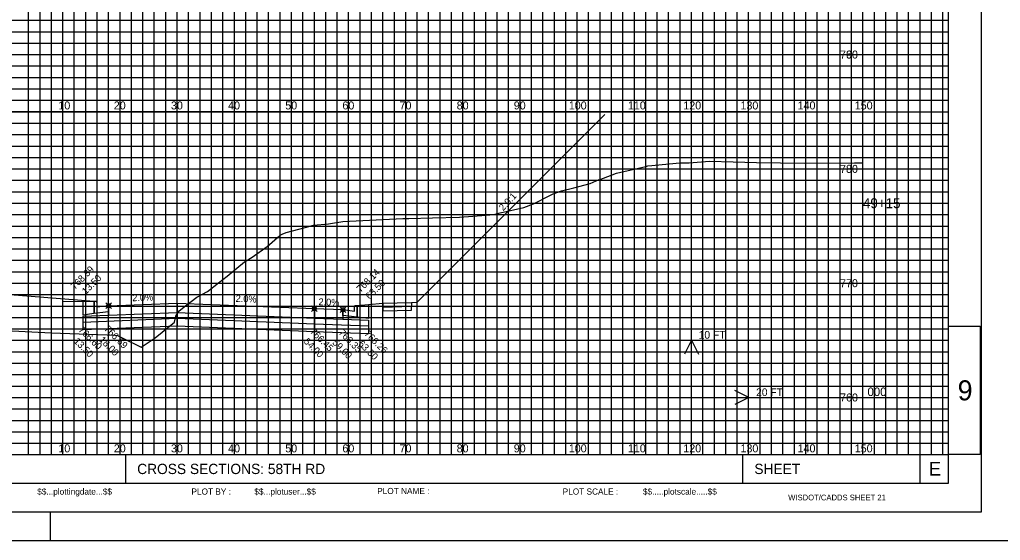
# Model space of a CAD drawing. Extents: x 578243 to 601557, y 174899 to 175559.
# Drawn here: x 600362.3 to 600533.9, y 174898.8 to 174989.9 of the extents above; entities that cross this region are included whole.
import ezdxf

# ---------------------------------------------------------------- set-up
doc = ezdxf.new("R2010")
doc.units = 0
for name, color, linetype in [('E_PROF_Grid', 7, 'Continuous'), ('E_PROF_GridMin', 7, 'Continuous'), ('P_CRDR_Label', 7, 'Continuous'), ('P_CRDR_Link', 7, 'Continuous'), ('P_E_XS_Ground', 7, 'Continuous'), ('P_RW_SlopeIntercepts', 7, 'Continuous'), ('P_XS_Text', 7, 'Continuous'), ('PLT_Sheet_Border', 7, 'Continuous'), ('PLT_Sheet_Info', 7, 'Continuous')]:
    doc.layers.add(name, color=color, linetype=linetype)

msp = doc.modelspace()

# ---------------------------------------------------------------- linework, layer by layer
at = {"layer": 'E_PROF_Grid'}
for p, q in [((600369.84, 174913.8), (600369.84, 175108.8)), ((600379.84, 174913.8), (600379.84, 175108.8)), ((600389.84, 174913.8), (600389.84, 175108.8)), ((600399.84, 174913.8), (600399.84, 175108.8)), ((600409.84, 174913.8), (600409.84, 175108.8)), ((600419.84, 174913.8), (600419.84, 175108.8)), ((600429.84, 174913.8), (600429.84, 175108.8)), ((600439.84, 174913.8), (600439.84, 175108.8)), ((600449.84, 174913.8), (600449.84, 175108.8)), ((600459.84, 174913.8), (600459.84, 175108.8)), ((600469.84, 174913.8), (600469.84, 175108.8)), ((600479.84, 174913.8), (600479.84, 175108.8)), ((600489.84, 174913.8), (600489.84, 175108.8)), ((600499.84, 174913.8), (600499.84, 175108.8)), ((600509.84, 174913.8), (600509.84, 175108.8)), ((600519.84, 174913.8), (600519.84, 175108.8)), ((600209.84, 174983.8), (600524.84, 174983.8)), ((600209.84, 174973.8), (600524.84, 174973.8)), ((600209.84, 174963.8), (600524.84, 174963.8)), ((600209.84, 174953.8), (600524.84, 174953.8)), ((600209.84, 174943.8), (600524.84, 174943.8)), ((600209.84, 174933.8), (600524.84, 174933.8)), ((600209.84, 174923.8), (600524.84, 174923.8))]:
    msp.add_line(p, q, dxfattribs=at)
at = {"layer": 'E_PROF_GridMin'}
for p, q in [((600363.84, 174913.8), (600363.84, 175108.8)), ((600365.84, 174913.8), (600365.84, 175108.8)), ((600367.84, 174913.8), (600367.84, 175108.8)), ((600371.84, 174913.8), (600371.84, 175108.8)), ((600373.84, 174913.8), (600373.84, 175108.8)), ((600375.84, 174913.8), (600375.84, 175108.8)), ((600377.84, 174913.8), (600377.84, 175108.8)), ((600381.84, 174913.8), (600381.84, 175108.8)), ((600383.84, 174913.8), (600383.84, 175108.8)), ((600385.84, 174913.8), (600385.84, 175108.8)), ((600387.84, 174913.8), (600387.84, 175108.8)), ((600391.84, 174913.8), (600391.84, 175108.8)), ((600393.84, 174913.8), (600393.84, 175108.8)), ((600395.84, 174913.8), (600395.84, 175108.8)), ((600397.84, 174913.8), (600397.84, 175108.8)), ((600401.84, 174913.8), (600401.84, 175108.8)), ((600403.84, 174913.8), (600403.84, 175108.8)), ((600405.84, 174913.8), (600405.84, 175108.8)), ((600407.84, 174913.8), (600407.84, 175108.8)), ((600411.84, 174913.8), (600411.84, 175108.8)), ((600413.84, 174913.8), (600413.84, 175108.8)), ((600415.84, 174913.8), (600415.84, 175108.8)), ((600417.84, 174913.8), (600417.84, 175108.8)), ((600421.84, 174913.8), (600421.84, 175108.8)), ((600423.84, 174913.8), (600423.84, 175108.8)), ((600425.84, 174913.8), (600425.84, 175108.8)), ((600427.84, 174913.8), (600427.84, 175108.8)), ((600431.84, 174913.8), (600431.84, 175108.8)), ((600433.84, 174913.8), (600433.84, 175108.8)), ((600435.84, 174913.8), (600435.84, 175108.8)), ((600437.84, 174913.8), (600437.84, 175108.8)), ((600441.84, 174913.8), (600441.84, 175108.8)), ((600443.84, 174913.8), (600443.84, 175108.8)), ((600445.84, 174913.8), (600445.84, 175108.8)), ((600447.84, 174913.8), (600447.84, 175108.8)), ((600451.84, 174913.8), (600451.84, 175108.8)), ((600453.84, 174913.8), (600453.84, 175108.8)), ((600455.84, 174913.8), (600455.84, 175108.8)), ((600457.84, 174913.8), (600457.84, 175108.8)), ((600461.84, 174913.8), (600461.84, 175108.8)), ((600463.84, 174913.8), (600463.84, 175108.8)), ((600465.84, 174913.8), (600465.84, 175108.8)), ((600467.84, 174913.8), (600467.84, 175108.8)), ((600471.84, 174913.8), (600471.84, 175108.8)), ((600473.84, 174913.8), (600473.84, 175108.8)), ((600475.84, 174913.8), (600475.84, 175108.8)), ((600477.84, 174913.8), (600477.84, 175108.8)), ((600481.84, 174913.8), (600481.84, 175108.8)), ((600483.84, 174913.8), (600483.84, 175108.8)), ((600485.84, 174913.8), (600485.84, 175108.8)), ((600487.84, 174913.8), (600487.84, 175108.8)), ((600491.84, 174913.8), (600491.84, 175108.8)), ((600493.84, 174913.8), (600493.84, 175108.8)), ((600495.84, 174913.8), (600495.84, 175108.8)), ((600497.84, 174913.8), (600497.84, 175108.8)), ((600501.84, 174913.8), (600501.84, 175108.8)), ((600503.84, 174913.8), (600503.84, 175108.8)), ((600505.84, 174913.8), (600505.84, 175108.8)), ((600507.84, 174913.8), (600507.84, 175108.8)), ((600511.84, 174913.8), (600511.84, 175108.8)), ((600513.84, 174913.8), (600513.84, 175108.8)), ((600515.84, 174913.8), (600515.84, 175108.8)), ((600517.84, 174913.8), (600517.84, 175108.8)), ((600521.84, 174913.8), (600521.84, 175108.8)), ((600523.84, 174913.8), (600523.84, 175108.8)), ((600209.84, 174989.8), (600524.84, 174989.8)), ((600209.84, 174987.8), (600524.84, 174987.8)), ((600209.84, 174985.8), (600524.84, 174985.8)), ((600209.84, 174981.8), (600524.84, 174981.8)), ((600209.84, 174979.8), (600524.84, 174979.8)), ((600209.84, 174977.8), (600524.84, 174977.8)), ((600209.84, 174975.8), (600524.84, 174975.8)), ((600209.84, 174971.8), (600524.84, 174971.8)), ((600209.84, 174969.8), (600524.84, 174969.8)), ((600209.84, 174967.8), (600524.84, 174967.8)), ((600209.84, 174965.8), (600524.84, 174965.8)), ((600209.84, 174961.8), (600524.84, 174961.8)), ((600209.84, 174959.8), (600524.84, 174959.8)), ((600209.84, 174957.8), (600524.84, 174957.8)), ((600209.84, 174955.8), (600524.84, 174955.8)), ((600209.84, 174951.8), (600524.84, 174951.8)), ((600209.84, 174949.8), (600524.84, 174949.8)), ((600209.84, 174947.8), (600524.84, 174947.8)), ((600209.84, 174945.8), (600524.84, 174945.8)), ((600209.84, 174941.8), (600524.84, 174941.8)), ((600209.84, 174939.8), (600524.84, 174939.8)), ((600209.84, 174937.8), (600524.84, 174937.8)), ((600209.84, 174935.8), (600524.84, 174935.8)), ((600209.84, 174931.8), (600524.84, 174931.8)), ((600209.84, 174929.8), (600524.84, 174929.8)), ((600209.84, 174927.8), (600524.84, 174927.8)), ((600209.84, 174925.8), (600524.84, 174925.8)), ((600209.84, 174921.8), (600524.84, 174921.8)), ((600209.84, 174919.8), (600524.84, 174919.8)), ((600209.84, 174917.8), (600524.84, 174917.8)), ((600209.84, 174915.8), (600524.84, 174915.8)), ((600527.19, 174898.8), (600537.19, 174898.8))]:
    msp.add_line(p, q, dxfattribs=at)
at = {"layer": 'P_CRDR_Label'}
for points in [[(600377.35, 174939.35), (600378.34, 174940.34)], [(600377.35, 174940.34), (600378.34, 174939.35)], [(600413.35, 174938.87), (600414.34, 174939.86)], [(600413.35, 174939.86), (600414.34, 174938.87)], [(600418.35, 174938.67), (600419.34, 174939.66)], [(600418.35, 174939.66), (600419.34, 174938.67)]]:
    msp.add_lwpolyline(points, dxfattribs=at)
for centre in [(600377.84, 174939.85), (600413.84, 174939.37), (600418.84, 174939.17)]:
    msp.add_circle(centre, 0.35, dxfattribs=at)
at = {"layer": 'P_CRDR_Link'}
msp.add_line((600464.69, 174973.31), (600431.84, 174940.46), dxfattribs=at)
for points in [[(600375.34, 174940.6), (600359.84, 174941.84)], [(600375.34, 174940.6), (600359.84, 174941.84)], [(600373.34, 174940.58), (600369.84, 174940.55)], [(600373.34, 174940.58), (600369.84, 174940.55)], [(600375.34, 174940.6), (600373.34, 174940.58)], [(600373.34, 174940.58), (600373.34, 174938.28)], [(600373.34, 174940.58), (600373.34, 174938.28)], [(600373.34, 174940.58), (600373.34, 174938.28)], [(600375.66, 174940.6), (600375.34, 174940.6)], [(600375.66, 174940.6), (600375.34, 174940.6)], [(600375.34, 174940.6), (600375.34, 174938.53)], [(600375.34, 174938.53), (600375.34, 174940.6)], [(600375.74, 174940.55), (600375.66, 174940.6)], [(600375.74, 174940.55), (600375.66, 174940.6)], [(600375.8, 174940.44), (600375.74, 174940.55)], [(600375.8, 174940.44), (600375.74, 174940.55)], [(600375.83, 174940.28), (600375.8, 174940.44)], [(600375.83, 174940.28), (600375.8, 174940.44)], [(600375.84, 174939.6), (600375.83, 174940.28)], [(600375.84, 174939.6), (600375.83, 174940.28)], [(600377.84, 174939.85), (600375.84, 174939.6)], [(600377.84, 174939.85), (600375.84, 174939.6)], [(600377.84, 174939.85), (600389.84, 174940.33)], [(600377.84, 174938.85), (600377.84, 174939.85)], [(600377.84, 174939.85), (600377.84, 174938.18)], [(600389.84, 174940.33), (600389.84, 174938.66)], [(600389.84, 174940.33), (600413.84, 174939.37)], [(600389.84, 174940.33), (600389.84, 174938.66)], [(600420.85, 174939.6), (600420.88, 174939.76)], [(600420.85, 174939.6), (600420.88, 174939.76)], [(600420.88, 174939.76), (600420.94, 174939.87)], [(600420.88, 174939.76), (600420.94, 174939.87)], [(600420.94, 174939.87), (600421.02, 174939.92)], [(600420.94, 174939.87), (600421.02, 174939.92)], [(600421.02, 174939.92), (600421.34, 174939.92)], [(600421.02, 174939.92), (600421.34, 174939.92)], [(600421.34, 174939.92), (600423.34, 174940.08)], [(600421.34, 174939.92), (600421.34, 174937.85)], [(600421.34, 174937.85), (600421.34, 174939.92)], [(600423.34, 174940.08), (600425.84, 174940.28)], [(600423.34, 174940.08), (600425.84, 174940.28)], [(600423.34, 174940.08), (600423.34, 174937.6)], [(600423.34, 174940.08), (600423.34, 174937.6)], [(600423.34, 174940.08), (600423.34, 174937.6)], [(600425.84, 174940.28), (600430.84, 174940.43)], [(600425.84, 174940.28), (600430.84, 174940.43)], [(600425.84, 174940.28), (600425.85, 174939.61)], [(600425.85, 174939.61), (600430.84, 174939.76)], [(600430.83, 174939.1), (600430.84, 174939.76)], [(600430.84, 174940.43), (600431.84, 174940.46)], [(600430.84, 174940.43), (600431.84, 174940.46)], [(600430.84, 174940.43), (600430.84, 174939.76)], [(600373.34, 174938.28), (600375.34, 174938.53)], [(600373.34, 174938), (600377.84, 174938.18)], [(600375.34, 174938.53), (600377.84, 174938.85)], [(600375.34, 174938.53), (600377.84, 174938.85)], [(600377.84, 174938.18), (600389.84, 174938.66)], [(600389.84, 174938.66), (600389.84, 174937.66)], [(600389.84, 174938.66), (600413.84, 174937.7)], [(600389.84, 174938.66), (600389.84, 174937.66)], [(600413.84, 174939.37), (600413.84, 174937.7)], [(600413.84, 174939.37), (600418.84, 174939.17)], [(600413.84, 174939.37), (600413.84, 174937.7)], [(600418.84, 174939.17), (600418.84, 174937.5)], [(600418.84, 174939.17), (600420.84, 174938.92)], [(600418.84, 174939.17), (600420.84, 174938.92)], [(600418.84, 174938.17), (600418.84, 174939.17)], [(600421.34, 174937.85), (600418.84, 174938.17)], [(600421.34, 174937.85), (600418.84, 174938.17)], [(600420.84, 174938.92), (600420.85, 174939.6)], [(600420.84, 174938.92), (600420.85, 174939.6)], [(600425.85, 174939.61), (600425.85, 174938.95)], [(600425.85, 174938.95), (600430.83, 174939.1)], [(600373.34, 174938), (600373.34, 174937)], [(600373.34, 174937), (600389.84, 174937.66)], [(600373.34, 174937), (600373.34, 174935.67)], [(600373.34, 174935.67), (600389.84, 174936.33)], [(600389.84, 174937.66), (600389.84, 174936.33)], [(600389.84, 174937.66), (600413.84, 174936.7)], [(600389.84, 174937.66), (600389.84, 174936.33)], [(600389.84, 174936.33), (600413.84, 174935.37)], [(600413.84, 174937.7), (600413.84, 174936.7)], [(600413.84, 174937.7), (600418.84, 174937.5)], [(600413.84, 174937.7), (600413.84, 174936.7)], [(600413.84, 174936.7), (600413.84, 174935.37)], [(600413.84, 174936.7), (600423.34, 174936.32)], [(600413.84, 174936.7), (600413.84, 174935.37)], [(600418.84, 174937.5), (600423.34, 174937.32)], [(600423.34, 174937.6), (600421.34, 174937.85)], [(600423.34, 174937.32), (600423.34, 174936.32)], [(600423.34, 174936.32), (600423.34, 174934.99)], [(600413.84, 174935.37), (600423.34, 174934.99)]]:
    msp.add_lwpolyline(points, dxfattribs=at)
at = {"layer": 'P_E_XS_Ground'}
msp.add_lwpolyline([(600359.84, 174935.54), (600367.8, 174935.14), (600377.57, 174934.75), (600378.93, 174934.68), (600379.38, 174934.67), (600380.33, 174934.19), (600383.51, 174932.6), (600385.99, 174934.24), (600389.38, 174936.95), (600389.62, 174938.05), (600390.15, 174938.93), (600391.04, 174939.66), (600393.29, 174941.36), (600395.14, 174942.35), (600397.06, 174943.88), (600398.57, 174945.03), (600401.64, 174947.52), (600402.96, 174948.37), (600405.59, 174950.24), (600407.8, 174952.15), (600408.19, 174952.4), (600408.91, 174952.66), (600412.24, 174953.56), (600413.68, 174953.97), (600416.3, 174954.18), (600418.81, 174954.62), (600429.3, 174955.09), (600430.39, 174955.14), (600434.54, 174955.21), (600439.26, 174955.33), (600443.92, 174955.68), (600445.24, 174955.81), (600446.33, 174956.09), (600450.5, 174957.03), (600452.22, 174957.68), (600455.64, 174959.44), (600457.07, 174959.95), (600459.24, 174960.49), (600462.09, 174961.24), (600463.67, 174961.92), (600463.69, 174961.87), (600466.73, 174963.05), (600471.84, 174964.23), (600472.22, 174964.33), (600472.92, 174964.41), (600477.14, 174964.78), (600477.87, 174964.83), (600479.42, 174964.88), (600482.98, 174965.14), (600487.12, 174965.03), (600491.23, 174964.94), (600499.6, 174964.79), (600508.35, 174964.83), (600509.84, 174964.86)], dxfattribs=at)
at = {"layer": 'P_RW_SlopeIntercepts'}
msp.add_line((600253.84, 174973.83), (600489.84, 174973.83), dxfattribs=at)
at = {"layer": 'PLT_Sheet_Border'}
for points in [[(600197.19, 174898.8), (600537.19, 174898.8), (600537.19, 175118.8), (600197.19, 175118.8)], [(600199.59, 174903.8), (600530.59, 174903.8), (600530.59, 175113.8), (600199.59, 175113.8)]]:
    msp.add_lwpolyline(points, close=True, dxfattribs=at)
at = {"layer": 'PLT_Sheet_Info'}
for p, q in [((600524.84, 174908.8), (600524.84, 175108.8)), ((600209.84, 174913.8), (600524.84, 174913.8)), ((600380.84, 174908.8), (600380.84, 174913.8)), ((600488.84, 174908.8), (600488.84, 174913.8)), ((600519.84, 174908.8), (600519.84, 174913.8)), ((600209.84, 174908.8), (600524.84, 174908.8)), ((600367.69, 174898.8), (600367.69, 174903.8)), ((600362.69, 174898.8), (600372.69, 174898.8))]:
    msp.add_line(p, q, dxfattribs=at)
msp.add_lwpolyline([(600524.84, 174936.3), (600530.34, 174936.3), (600530.34, 174913.8), (600524.84, 174913.8)], close=True, dxfattribs=at)
for points in [[(600479.84, 174933.84), (600478.6, 174931.36)], [(600479.84, 174923.8), (600479.84, 174933.84), (600481.08, 174931.36)], [(600489.89, 174923.8), (600487.4, 174925.04)], [(600479.84, 174923.8), (600489.89, 174923.8), (600487.4, 174922.55)]]:
    msp.add_lwpolyline(points, dxfattribs=at)

# ---------------------------------------------------------------- texts
at = {"layer": 'P_CRDR_Label'}
for s, rotation, p in [('2.0:1', 46.711, (600446.88, 174956.37)), ('768.39', 45, (600371.93, 174942.62)), ('13.50', 45, (600373.87, 174941.74)), ('768.14', 45, (600421.93, 174942.12)), ('63.50', 45, (600423.51, 174940.88)), ('2.0%', 2.2906, (600382, 174940.63)), ('2.0%', 357.7094, (600400.05, 174940.54)), ('2.0%', 357.7094, (600414.55, 174939.96)), ('766.60', 315, (600372.49, 174935.52)), ('766.69', 315, (600376.99, 174935.7)), ('766.45', 315, (600412.99, 174935.22)), ('766.35', 315, (600417.99, 174935.02)), ('766.26', 315, (600422.49, 174934.84)), ('13.50', 315, (600371.64, 174933.55)), ('18.00', 315, (600376.08, 174933.79)), ('54.00', 315, (600411.9, 174933.49)), ('59.00', 315, (600416.89, 174933.29)), ('63.50', 315, (600421.43, 174933.08))]:
    msp.add_text(s, height=1.2, rotation=rotation, dxfattribs=at).set_placement(p)
at = {"layer": 'P_XS_Text'}
for s, height, p in [('790', 1.4, (600505.84, 174983.1)), ('760', 1.4, (600505.84, 174983.1)), ('10', 1.4, (600369.05, 174974.2)), ('20', 1.4, (600378.75, 174974.2)), ('30', 1.4, (600388.75, 174974.2)), ('40', 1.4, (600398.75, 174974.2)), ('50', 1.4, (600408.75, 174974.2)), ('60', 1.4, (600418.75, 174974.2)), ('70', 1.4, (600428.75, 174974.2)), ('80', 1.4, (600438.75, 174974.2)), ('90', 1.4, (600448.74, 174974.2)), ('100', 1.4, (600458.37, 174974.2)), ('110', 1.4, (600468.71, 174974.2)), ('120', 1.4, (600478.41, 174974.2)), ('130', 1.4, (600488.41, 174974.2)), ('140', 1.4, (600498.41, 174974.2)), ('150', 1.4, (600508.41, 174974.2)), ('780', 1.4, (600505.84, 174963.1)), ('49+15', 1.75, (600509.84, 174956.92)), ('770', 1.4, (600505.84, 174943.1)), ('760', 1.4, (600505.84, 174923.1)), ('10', 1.4, (600369.05, 174914.2)), ('20', 1.4, (600378.75, 174914.2)), ('30', 1.4, (600388.75, 174914.2)), ('40', 1.4, (600398.75, 174914.2)), ('50', 1.4, (600408.75, 174914.2)), ('60', 1.4, (600418.75, 174914.2)), ('70', 1.4, (600428.75, 174914.2)), ('80', 1.4, (600438.75, 174914.2)), ('90', 1.4, (600448.74, 174914.2)), ('100', 1.4, (600458.37, 174914.2)), ('110', 1.4, (600468.71, 174914.2)), ('120', 1.4, (600478.41, 174914.2)), ('130', 1.4, (600488.41, 174914.2)), ('140', 1.4, (600498.41, 174914.2)), ('150', 1.4, (600508.41, 174914.2))]:
    msp.add_text(s, height=height, rotation=360, dxfattribs=at).set_placement(p)
at = {"layer": 'PLT_Sheet_Info'}
for s, height, p in [('  10 FT', 1.347, (600480.09, 174934.09)), ('9', 3.5, (600526.42, 174923.3)), ('  20 FT', 1.347, (600490.14, 174924.05)), ('     000', 1.5, (600507.84, 174924.05)), ('E', 2.4, (600521.36, 174910.12)), ('CROSS SECTIONS: 58TH RD                           ', 1.8, (600382.84, 174910.4)), ('SHEET ', 1.8, (600490.84, 174910.4)), ('PLOT NAME :                      ', 1.08, (600424.84, 174906.9)), ('PLOT SCALE : ', 1.08, (600457.3, 174906.8)), ('$$.....plotscale.....$$', 1.08, (600471.34, 174906.8)), ('WISDOT/CADDS SHEET 21', 1, (600496.76, 174905.8))]:
    msp.add_text(s, height=height, dxfattribs=at).set_placement(p)
for s, p in [('$$...plottingdate...$$', (600365.34, 174906.8)), ('PLOT BY :', (600392.34, 174906.8)), ('$$...plotuser...$$', (600403.34, 174906.8))]:
    msp.add_text(s, height=1.08, rotation=360, dxfattribs=at).set_placement(p)

doc.saveas('drawing.dxf')
